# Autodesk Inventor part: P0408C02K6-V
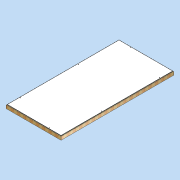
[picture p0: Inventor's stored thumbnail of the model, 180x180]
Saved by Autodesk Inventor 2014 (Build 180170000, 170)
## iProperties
Created: 2011-04
Part Number: P0408C02K6-V
Document SubType Name: Modeling
Designer: david.appleford
Density: 0.199369 g/cm^3
Description: 1w x 2w 02 Ceiling Panel - 6 Locks
Mass: 45000 g
Surface Area: 60385.3 cm^2
Volume: 225712 cm^3
Cost Center: £135.00
Material: Generic
Appearance: Wood (Pine)
Justset: False
Title: 1w x 2w 02 Ceiling Panel - 6 Locks
Author: david.appleford
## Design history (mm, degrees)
sketch "Sketch1"
  geometry: L1 (0, 0)-(1220, 0); L2 (1220, 0)-(1220, 2440); L3 (1220, 2440)-(0, 2440); L4 (0, 2440)-(0, 0); L5 (34, 2406)-(1186, 2406); L6 (1186, 2406)-(1186, 34); L7 (1186, 34)-(34, 34); L8 (34, 34)-(34, 2406)
  constraints: 16 end point, 4 parallel, 2 perpendicular, 1 horizontal, 3 other
  dimensions: "d0" = 1220 distance between parallel lines of L2 L4 (= w); "d1" = 2440 distance between parallel lines of L1 L3 (= 2 x w); "d2" = 34 distance between parallel lines of L5 L3 (= 0.5 x t)
extrude "Extrusion1" new body sketch "Sketch1" distance "d3" = 68 (= t); taper "d4" = 0 deg
sketch "Sketch2"
  geometry: L1 (1186, 2406)-(1186, 34) reference; L2 (34, 2406)-(1186, 2406) reference; L3 (34, 34)-(34, 2406) reference; L4 (1186, 34)-(34, 34) reference; L5 (1176, 2396)-(1176, 44); L6 (1176, 44)-(44, 44); L7 (44, 44)-(44, 2396); L8 (44, 2396)-(1176, 2396); 1 further point
  constraints: 8 end point, 3 other
  dimensions: "d5" = 10 distance between parallel lines of L8 L2
extrude "Extrusion2" join sketch "Sketch2" distance "d6" = 9; taper "d7" = 0 deg
sketch "Sketch3"
  geometry: L1 (-44, 2396)-(-1176, 2396) reference; L2 (-1176, 2396)-(-1176, 44) reference; L3 (-44, 44)-(-44, 2396) reference; L4 (-1176, 44)-(-44, 44) reference; 1 further point
extrude "Extrusion3" join sketch "Sketch3" distance "d8" = 6 (= sw); taper "d9" = 0 deg
sketch "Sketch4"
  geometry: L1 (34, 2406)-(1186, 2406) reference; L2 (1186, 2406)-(1186, 34) reference; L3 (1186, 34)-(34, 34) reference; L4 (34, 34)-(34, 2406) reference; 7 further points
  constraints: 2 vertical alignment
  dimensions: "d10" = 28 distance from line of point (305, 2378) L1 (= k); "d12" = 28 distance from line of L3 point (915, 62) (= k); "d13" = 28 distance from line of point (62, 305) L4 (= k); "d14" = 305 horizontal distance of point (305, 2378) point (0, 0) (= 0.25 x w); "d15" = 610 horizontal distance of point (915, 62) point (305, 2378) (= 0.5 x w); "d16" = 305 vertical distance of point (62, 305) point (0, 0) (= 0.25 x w); "d17" = 1220 distance of point (62, 305) point (62, 1525) (= w); "d19" = 610 vertical distance of point (1158, 915) point (62, 305) (= 0.5 x w); "d20" = 1220 distance of point (1158, 915) point (1158, 2135) (= w)
hole "Hole1" sketch "Sketch4" at (305, 2378), (62, 1525), (62, 305), (1158, 2135), (1158, 915), (915, 62) diameter "d22" = 12 (= hd); stored, may be unused: countersink angle "d26" = 90 deg, drill point angle "d28" = 118 deg; dims "d23" = 6, "d24" = 4, "d25" = 2, "d27" = 8
chamfer "Chamfer1" distance "d29" = 3; stored, may be unused: second distance "d30" = 2, angle "d31" = 45 deg
body "Solid1"
node "Projected Loop1"
other parameters: "w" = 1220 [user parameter; used in 8 equation terms], "t" = 68 [user parameter; used in 2 equation terms], "e" = 16 [user parameter], "sw" = 6 [user parameter; used in 1 equation term], "sc" = 9 [user parameter], "sf" = 12 [user parameter], "k" = 28 [user parameter; used in 3 equation terms], "hd" = 12 [user parameter; used in 1 equation term]
